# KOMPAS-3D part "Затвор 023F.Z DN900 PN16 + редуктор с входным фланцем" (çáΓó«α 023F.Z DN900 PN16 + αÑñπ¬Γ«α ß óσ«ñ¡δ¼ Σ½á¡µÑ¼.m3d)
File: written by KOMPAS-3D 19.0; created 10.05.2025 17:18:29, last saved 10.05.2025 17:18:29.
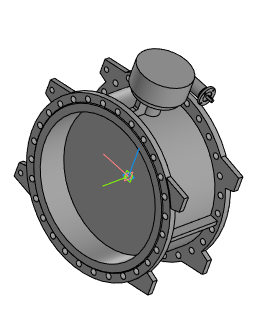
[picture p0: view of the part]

Document properties: Полное имя файла: Затвор 023F.Z DN900 PN16 + редуктор с входным фланцем.a3d

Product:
- Part/product: Затвор 023F.Z DN900 PN16 + редуктор с входным фланцем
    Масса: 1058.97

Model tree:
1. Операция без истории:1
